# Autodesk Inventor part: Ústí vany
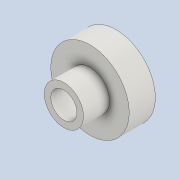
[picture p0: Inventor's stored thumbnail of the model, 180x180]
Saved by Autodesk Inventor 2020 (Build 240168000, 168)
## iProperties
Created: 2025-03
Part Number: Ústí vany
Material: Ocel
Document SubType Name: Modeling
Designer: doma
Density: 7.85 g/cm^3
Appearance: Ocel
Author: doma
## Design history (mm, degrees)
sketch "Náčrt1"
  geometry: C1 r 15 at (0, 0); C2 r 5 at (0, 0); 1 further point
  constraints: 2 centre point, 2 coincident
  dimensions: "d0" = 30 diameter of C1; "d1" = 10 diameter of C2
extrude "Vysunutí1" new body sketch "Náčrt1" distance "d2" = 10; taper "d3" = 0 deg
sketch "Náčrt2"
  geometry: C1 r 7.5 at (0, 0); C2 r 5 at (0, 0) reference; 1 further point
  constraints: 1 centre point, 1 coincident
  dimensions: "d4" = 15 diameter of C1
extrude "Vysunutí2" join sketch "Náčrt2" distance "d5" = 10; taper "d6" = 0 deg
node "Těleso1"
